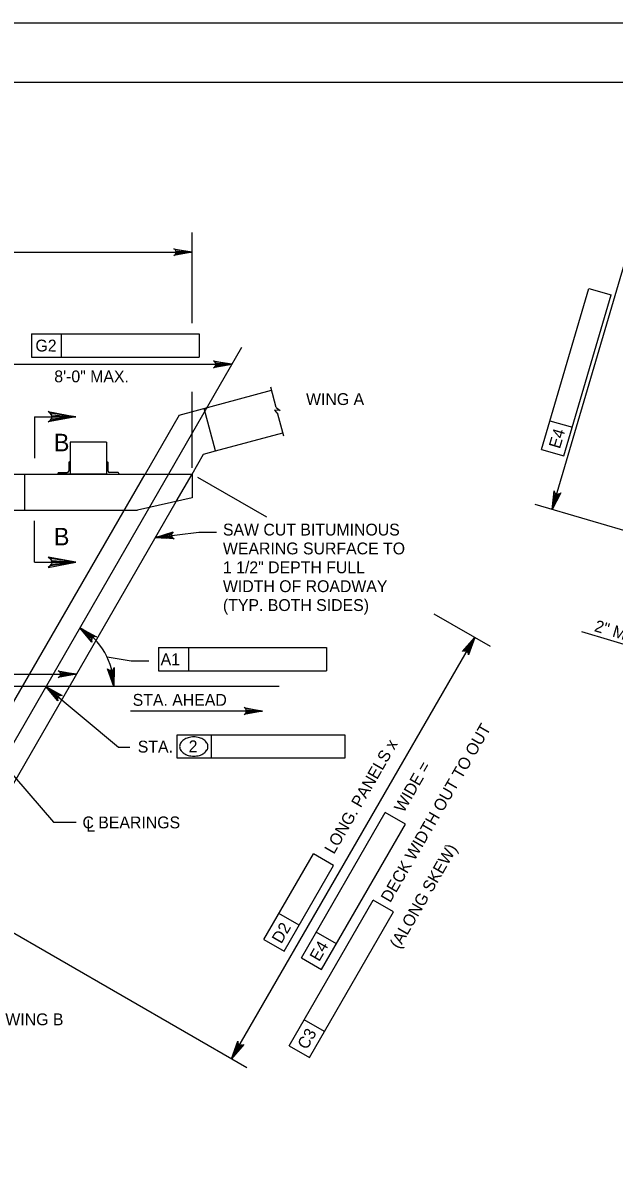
# Model space of a CAD drawing. Extents: x 638268 to 640277, y 295465 to 298435.
# Drawn here: x 639640.5 to 639790.3, y 298145.6 to 298435.5 of the extents above; entities that cross this region are included whole.
import ezdxf

# ---------------------------------------------------------------- set-up
doc = ezdxf.new("R2010")
doc.units = 0
for name, color, linetype in [('2', 7, 'Continuous'), ('3', 7, 'Continuous'), ('4', 7, 'Continuous'), ('PLT-BNDY', 7, 'Continuous')]:
    doc.layers.add(name, color=color, linetype=linetype)

msp = doc.modelspace()

# ---------------------------------------------------------------- linework, layer by layer
at = {"layer": '2'}
for p, q in [((639316.46, 298420.46), (640102.46, 298420.46)), ((639680.12, 298336.12), (639703.55, 298342.4)), ((639643.45, 298335.68), (639643.45, 298325.2)), ((639643.45, 298335.68), (639653.93, 298335.68)), ((639680.12, 298336.12), (639671.49, 298321.18)), ((639689.36, 298327.03), (639686.47, 298337.83)), ((639689.36, 298327.03), (639706.44, 298331.61)), ((639661.75, 298329.27), (639652.51, 298329.27)), ((639652.51, 298329.27), (639652.51, 298321.18)), ((639661.75, 298329.27), (639661.75, 298321.18)), ((639686.33, 298326.22), (639689.36, 298327.03)), ((639652.15, 298324.09), (639652.15, 298321.91)), ((639652.33, 298324.27), (639652.51, 298324.27)), ((639652.51, 298324.27), (639652.51, 298321.18)), ((639661.93, 298324.27), (639661.75, 298324.27)), ((639661.75, 298324.27), (639661.75, 298321.18)), ((639662.11, 298324.09), (639662.11, 298321.91)), ((639683.42, 298321.18), (639686.33, 298326.22)), ((639484.75, 298321.18), (639683.42, 298321.18)), ((639609.87, 298214.45), (639671.49, 298321.18)), ((639640.96, 298321.18), (639640.96, 298312.06)), ((639649.42, 298321.36), (639649.42, 298321.18)), ((639652.51, 298321.18), (639649.42, 298321.18)), ((639649.6, 298321.54), (639651.79, 298321.54)), ((639661.75, 298321.18), (639652.51, 298321.18)), ((639661.75, 298321.18), (639664.84, 298321.18)), ((639664.66, 298321.54), (639662.48, 298321.54)), ((639664.84, 298321.36), (639664.84, 298321.18)), ((639679.42, 298314.26), (639683.42, 298321.18)), ((639683.42, 298321.18), (639683.42, 298315.15)), ((639683.42, 298315.15), (639669.57, 298312.06)), ((639624.79, 298219.62), (639679.42, 298314.26)), ((639531.9, 298312.06), (639669.57, 298312.06)), ((639643.45, 298298.84), (639643.45, 298309.32)), ((639643.45, 298298.84), (639653.93, 298298.84))]:
    msp.add_line(p, q, dxfattribs=at)
for points in [[(639653.93, 298335.68), (639646.94, 298334.37), (639647.48, 298334.74), (639647.76, 298335.21), (639647.84, 298335.68), (639647.76, 298336.15), (639647.48, 298336.62), (639646.94, 298336.99), (639653.93, 298335.68), (639647.48, 298336.62), (639647.76, 298336.15), (639653.93, 298335.68), (639647.84, 298335.68), (639647.76, 298335.21), (639653.93, 298335.68), (639647.48, 298334.74)], [(639653.93, 298298.84), (639646.94, 298300.15), (639647.48, 298299.77), (639647.76, 298299.31), (639647.84, 298298.84), (639647.76, 298298.37), (639647.48, 298297.9), (639646.94, 298297.53), (639653.93, 298298.84), (639647.48, 298297.9), (639647.76, 298298.37), (639653.93, 298298.84), (639647.84, 298298.84), (639647.76, 298299.31), (639653.93, 298298.84), (639647.48, 298299.77)]]:
    msp.add_lwpolyline(points, dxfattribs=at)
for centre, radius, start, end in [((639652.33, 298324.09), 0.182, 90, 179.9984), ((639661.93, 298324.09), 0.182, 0.0016, 90), ((639649.6, 298321.36), 0.182, 90, 179.9984), ((639651.79, 298321.91), 0.364, 270, 359.9984), ((639662.48, 298321.91), 0.364, 180.0016, 270), ((639664.66, 298321.36), 0.182, 0.0016, 90)]:
    msp.add_arc(centre, radius, start, end, dxfattribs=at)
at = {"layer": '3'}
for p, q in [((639774.66, 298312.22), (639794.68, 298380.2)), ((639704.71, 298338.04), (639703.34, 298343.17)), ((639705.76, 298337.26), (639704.27, 298337.35)), ((639704.27, 298337.35), (639705.16, 298336.37)), ((639704.71, 298338.04), (639705.76, 298337.26)), ((639706.66, 298330.77), (639705.16, 298336.37)), ((639827.62, 298296.62), (639770.34, 298313.49))]:
    msp.add_line(p, q, dxfattribs=at)
msp.add_lwpolyline([(639775.02, 298315.24), (639775.98, 298314.96), (639774.66, 298312.22)], close=True, dxfattribs=at)
at = {"layer": '4'}
for p, q in [((639683.42, 298359.43), (639683.42, 298382.39)), ((639484.75, 298377.4), (639683.42, 298377.4)), ((639771.94, 298327.43), (639783.96, 298368.22)), ((639783.96, 298368.22), (639789.62, 298366.55)), ((639777.61, 298325.76), (639789.62, 298366.55)), ((639642.7, 298356.69), (639685.22, 298356.69)), ((639642.7, 298356.69), (639642.7, 298350.78)), ((639650.26, 298356.69), (639650.26, 298350.78)), ((639685.22, 298356.69), (639685.22, 298350.78)), ((639695.94, 298353.2), (639601.92, 298190.35)), ((639642.7, 298350.78), (639685.22, 298350.78)), ((639632.25, 298348.98), (639693.5, 298348.98)), ((639683.42, 298322.79), (639683.42, 298342.05)), ((639774.08, 298334.68), (639779.75, 298333.02)), ((639771.94, 298327.43), (639777.61, 298325.76)), ((639684.77, 298320.4), (639702.24, 298310.31)), ((639674.14, 298305.1), (639685.16, 298306.43)), ((639685.16, 298306.43), (639689.56, 298306.43)), ((639744.7, 298285.8), (639758.93, 298277.58)), ((639809.27, 298273.2), (639782.13, 298281.19)), ((639693.42, 298173.11), (639755.04, 298279.83)), ((639661.86, 298274.9), (639668, 298273.86)), ((639674.93, 298277.23), (639717.45, 298277.23)), ((639674.93, 298277.23), (639674.93, 298271.33)), ((639682.49, 298277.23), (639682.49, 298271.33)), ((639717.45, 298277.23), (639717.45, 298271.33)), ((639668, 298273.86), (639672.48, 298273.86)), ((639458.48, 298270.51), (639654.17, 298270.51)), ((639674.93, 298271.33), (639717.45, 298271.33)), ((639705.49, 298267.4), (639413.2, 298267.4)), ((639646.4, 298267.4), (639664.77, 298252.05)), ((639701.24, 298261.16), (639667.85, 298261.16)), ((639679.61, 298249.23), (639679.61, 298255.13)), ((639679.61, 298255.13), (639722.14, 298255.13)), ((639688.36, 298249.23), (639688.36, 298255.13)), ((639722.14, 298255.13), (639722.14, 298249.23)), ((639664.77, 298252.05), (639667.6, 298252.05)), ((639722.14, 298249.23), (639679.61, 298249.23)), ((639635.27, 298248.12), (639648.31, 298233.03)), ((639711.1, 298198.62), (639732.36, 298235.44)), ((639737.47, 298232.48), (639732.36, 298235.44)), ((639648.31, 298233.03), (639654.06, 298233.03)), ((639716.21, 298195.66), (639737.47, 298232.48)), ((639701.62, 298203.33), (639714.14, 298225.02)), ((639719.25, 298222.06), (639714.14, 298225.02)), ((639706.73, 298200.37), (639719.25, 298222.06)), ((639623.15, 298213.67), (639697.31, 298170.86)), ((639708.04, 298176.4), (639729.3, 298213.22)), ((639734.41, 298210.27), (639729.3, 298213.22)), ((639710.51, 298206.92), (639705.4, 298209.88)), ((639713.15, 298173.44), (639734.41, 298210.27)), ((639719.99, 298202.21), (639714.88, 298205.17)), ((639701.62, 298203.33), (639706.73, 298200.37)), ((639711.1, 298198.62), (639716.21, 298195.66)), ((639716.93, 298179.99), (639711.82, 298182.95)), ((639708.04, 298176.4), (639713.15, 298173.44))]:
    msp.add_line(p, q, dxfattribs=at)
for points in [[(639683.42, 298377.4), (639678.76, 298376.53), (639679.12, 298376.77), (639679.3, 298377.09), (639679.36, 298377.4), (639679.3, 298377.71), (639679.12, 298378.02), (639678.76, 298378.27), (639683.42, 298377.4), (639679.12, 298378.02), (639679.3, 298377.71), (639683.42, 298377.4), (639679.36, 298377.4), (639679.3, 298377.09), (639683.42, 298377.4), (639679.12, 298376.77)], [(639693.5, 298348.98), (639688.84, 298348.1), (639689.2, 298348.35), (639689.39, 298348.66), (639689.44, 298348.98), (639689.39, 298349.29), (639689.2, 298349.6), (639688.84, 298349.85), (639693.5, 298348.98), (639689.2, 298349.6), (639689.39, 298349.29), (639693.5, 298348.98), (639689.44, 298348.98), (639689.39, 298348.66), (639693.5, 298348.98), (639689.2, 298348.35)], [(639774.66, 298312.22), (639775.14, 298316.94), (639775.27, 298316.52), (639775.52, 298316.26), (639775.8, 298316.12), (639776.12, 298316.08), (639776.47, 298316.17), (639776.81, 298316.44), (639774.66, 298312.22), (639776.47, 298316.17), (639776.12, 298316.08), (639774.66, 298312.22), (639775.8, 298316.12), (639775.52, 298316.26), (639774.66, 298312.22), (639775.27, 298316.52)], [(639674.14, 298305.1), (639678.66, 298306.53), (639678.34, 298306.24), (639678.19, 298305.9), (639678.17, 298305.59), (639678.26, 298305.28), (639678.49, 298305), (639678.87, 298304.79), (639674.14, 298305.1), (639678.49, 298305), (639678.26, 298305.28), (639674.14, 298305.1), (639678.17, 298305.59), (639678.19, 298305.9), (639674.14, 298305.1), (639678.34, 298306.24)], [(639655, 298282.27), (639659.16, 298279.99), (639658.72, 298280.03), (639658.38, 298279.9), (639658.14, 298279.69), (639657.99, 298279.42), (639657.93, 298279.06), (639658.05, 298278.64), (639655, 298282.27), (639657.93, 298279.06), (639657.99, 298279.42), (639655, 298282.27), (639658.14, 298279.69), (639658.38, 298279.9), (639655, 298282.27), (639658.72, 298280.03)], [(639755.04, 298279.83), (639753.46, 298275.36), (639753.43, 298275.8), (639753.25, 298276.11), (639753, 298276.31), (639752.71, 298276.42), (639752.34, 298276.42), (639751.95, 298276.23), (639755.04, 298279.83), (639752.34, 298276.42), (639752.71, 298276.42), (639755.04, 298279.83), (639753, 298276.31), (639753.25, 298276.11), (639755.04, 298279.83), (639753.43, 298275.8)], [(639663.58, 298267.41), (639661.98, 298271.87), (639662.29, 298271.56), (639662.62, 298271.43), (639662.94, 298271.42), (639663.24, 298271.52), (639663.52, 298271.76), (639663.71, 298272.15), (639663.58, 298267.41), (639663.52, 298271.76), (639663.24, 298271.52), (639663.58, 298267.41), (639662.94, 298271.42), (639662.62, 298271.43), (639663.58, 298267.41), (639662.29, 298271.56)], [(639654.17, 298270.51), (639649.51, 298269.64), (639649.86, 298269.88), (639650.05, 298270.2), (639650.1, 298270.51), (639650.05, 298270.82), (639649.86, 298271.13), (639649.51, 298271.38), (639654.17, 298270.51), (639649.86, 298271.13), (639650.05, 298270.82), (639654.17, 298270.51), (639650.1, 298270.51), (639650.05, 298270.2), (639654.17, 298270.51), (639649.86, 298269.88)], [(639646.4, 298267.4), (639650.54, 298265.08), (639650.11, 298265.12), (639649.76, 298265), (639649.52, 298264.79), (639649.36, 298264.52), (639649.3, 298264.16), (639649.42, 298263.74), (639646.4, 298267.4), (639649.3, 298264.16), (639649.36, 298264.52), (639646.4, 298267.4), (639649.52, 298264.79), (639649.76, 298265), (639646.4, 298267.4), (639650.11, 298265.12)], [(639701.24, 298261.16), (639696.58, 298260.28), (639696.94, 298260.53), (639697.13, 298260.84), (639697.18, 298261.16), (639697.13, 298261.47), (639696.94, 298261.78), (639696.58, 298262.03), (639701.24, 298261.16), (639696.94, 298261.78), (639697.13, 298261.47), (639701.24, 298261.16), (639697.18, 298261.16), (639697.13, 298260.84), (639701.24, 298261.16), (639696.94, 298260.53)], [(639693.42, 298173.11), (639694.99, 298177.58), (639695.02, 298177.14), (639695.2, 298176.83), (639695.45, 298176.62), (639695.75, 298176.51), (639696.11, 298176.52), (639696.5, 298176.71), (639693.42, 298173.11), (639696.11, 298176.52), (639695.75, 298176.51), (639693.42, 298173.11), (639695.45, 298176.62), (639695.2, 298176.83), (639693.42, 298173.11), (639695.02, 298177.14)]]:
    msp.add_lwpolyline(points, dxfattribs=at)
for points in [[(639690.67, 298349.45), (639690.67, 298348.5), (639693.5, 298348.98)], [(639677.01, 298304.97), (639676.9, 298305.91), (639674.14, 298305.1)], [(639753.1, 298277.48), (639753.97, 298276.98), (639755.04, 298279.83)], [(639694.48, 298175.95), (639695.35, 298175.45), (639693.42, 298173.11)]]:
    msp.add_lwpolyline(points, close=True, dxfattribs=at)
for centre, radius, start, end in [((639646.4, 298267.4), 17.18, 0.0029, 59.9982), ((639683.46, 298250.73), 3.82, 105.6708, 124.109), ((639683.85, 298249.33), 5.27, 90, 105.6708), ((639683.85, 298249.33), 5.27, 74.3292, 90), ((639684.24, 298250.73), 3.82, 55.891, 74.3292), ((639681.94, 298252.17), 1.68, 148.5507, 180), ((639681.94, 298252.17), 1.68, 180, 211.4493), ((639682.86, 298251.61), 2.75, 124.109, 148.5507), ((639684.84, 298251.61), 2.75, 31.4493, 55.891), ((639685.76, 298252.17), 1.68, 0, 31.4493), ((639685.76, 298252.17), 1.68, 328.5507, 0), ((639682.86, 298252.73), 2.75, 211.4493, 235.891), ((639683.46, 298253.61), 3.82, 235.891, 254.3292), ((639683.85, 298255.01), 5.27, 254.3292, 270), ((639683.85, 298255.01), 5.27, 270, 285.6708), ((639684.24, 298253.61), 3.82, 285.6708, 304.109), ((639684.84, 298252.73), 2.75, 304.109, 328.5507)]:
    msp.add_arc(centre, radius, start, end, dxfattribs=at)
at = {"layer": 'PLT-BNDY'}
msp.add_lwpolyline([(639276.46, 298435.46), (640117.46, 298435.46), (640117.46, 297841.46), (639276.46, 297841.46)], close=True, dxfattribs=at)

# ---------------------------------------------------------------- texts
at = {"layer": '4'}
for s, height, rotation, p in [('G2', 3, 359.9382, (639643.73, 298352.23)), ('8\'-0" MAX.', 3, 359.9382, (639648.5, 298344.43)), ('E4', 3, 73.5262, (639776.59, 298327.43)), ('B', 4.43, 360, (639648.39, 298326.95)), ('2" MIN.', 3, 343.588, (639785.12, 298281.43)), ('A1', 3, 359.9382, (639675.44, 298272.78)), ('DECK WIDTH OUT TO OUT', 3, 60, (639733.62, 298212.45)), ('LONG. PANELS x', 3, 60, (639719.34, 298224.71)), ('WIDE =', 3, 60, (639737.01, 298235.23)), ('(ALONG SKEW)', 3, 60, (639735.89, 298200.72)), ('D2', 3, 59.9382, (639706.02, 298202.03)), ('E4', 3, 59.9382, (639715.61, 298197.53)), ('C3', 3, 59.9382, (639712.49, 298175.21))]:
    msp.add_text(s, height=height, rotation=rotation, dxfattribs=at).set_placement(p)
for s, height, p in [('WING A', 3, (639712.29, 298338.67)), ('B', 4.43, (639648.39, 298303.13)), ('SAW CUT BITUMINOUS', 3, (639691.23, 298305.62)), ('WEARING SURFACE TO', 3, (639691.23, 298300.84)), ('1 1/2" DEPTH FULL', 3, (639691.23, 298296.06)), ('WIDTH OF ROADWAY', 3, (639691.23, 298291.28)), ('(TYP. BOTH SIDES)', 3, (639691.23, 298286.5)), ('STA. AHEAD', 3, (639668.36, 298262.49)), ('STA.', 3, (639669.65, 298250.65)), ('2', 3, (639682.55, 298250.71)), ('C BEARINGS', 3, (639655.64, 298231.45)), ('L', 3, (639656.63, 298230.61)), ('WING B', 3, (639636.11, 298181.58))]:
    msp.add_text(s, height=height, dxfattribs=at).set_placement(p)

doc.saveas('drawing.dxf')
